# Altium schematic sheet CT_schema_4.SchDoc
size 278 x 236 mm
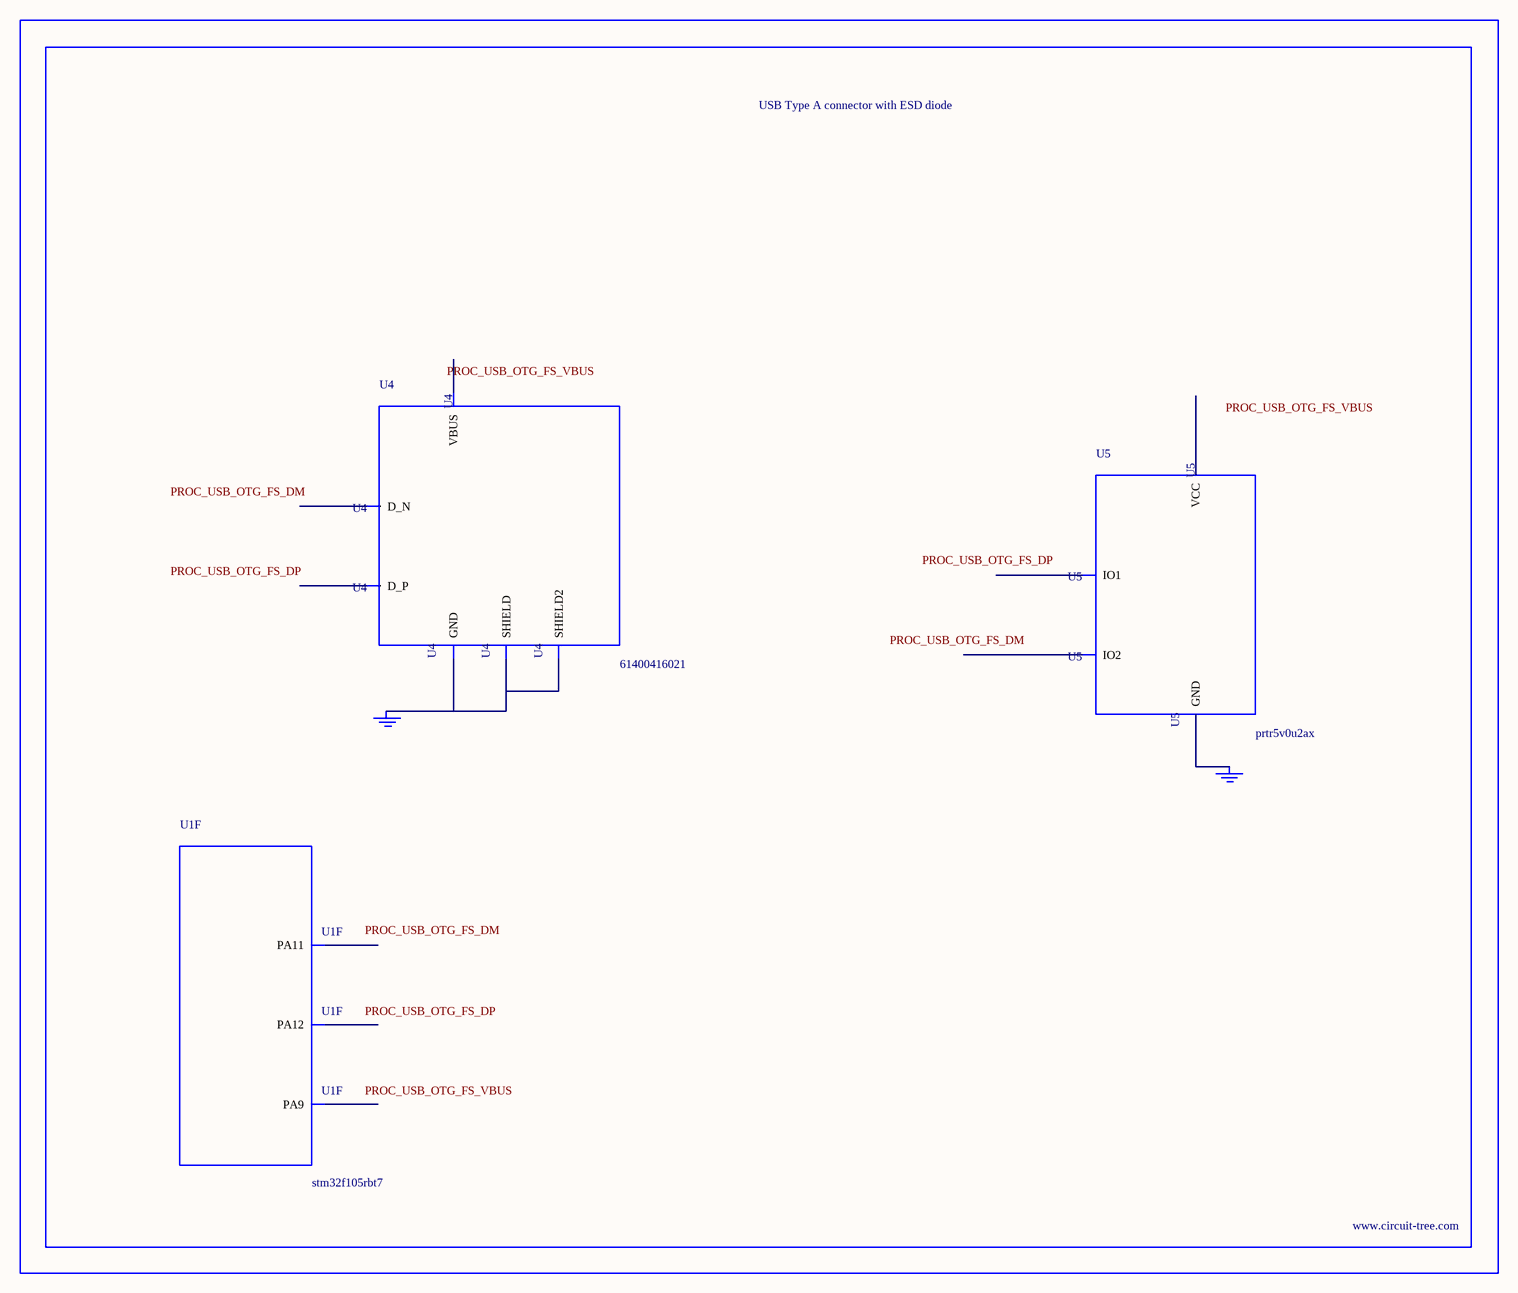
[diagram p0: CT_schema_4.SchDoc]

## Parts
BORDER3  (no value)
GND_INSTANCE_3_0  (no value)
GND_INSTANCE_3_1  (no value)
U1  stm32f105rbt7  [LQFP64]  (part F of 7)
U4  61400416021  [USB-A-H]
U5  prtr5v0u2ax  [SOT143B]

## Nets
NetGND_INSTANCE_3_0_0: GND_INSTANCE_3_0.0(GND) U4.4(GND) U4.5(SHIELD) U4.6(SHIELD2)
NetGND_INSTANCE_3_1_0: GND_INSTANCE_3_1.0(GND) U5.1(GND)

Not connected (* = marked no-connect by the designer): U1 42(PA9) 44(PA11) 45(PA12); U4 1(VBUS) 2(D_N) 3(D_P); U5 2(IO1) 3(IO2) 4(VCC)

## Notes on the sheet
- Labels drawn without touching a wire or pin: PROC_USB_OTG_FS_DM, PROC_USB_OTG_FS_DP, PROC_USB_OTG_FS_VBUS

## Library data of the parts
BORDER3 = BORDER_PAGE3
GND_INSTANCE_3_0 GND_INSTANCE_3_1 = GND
